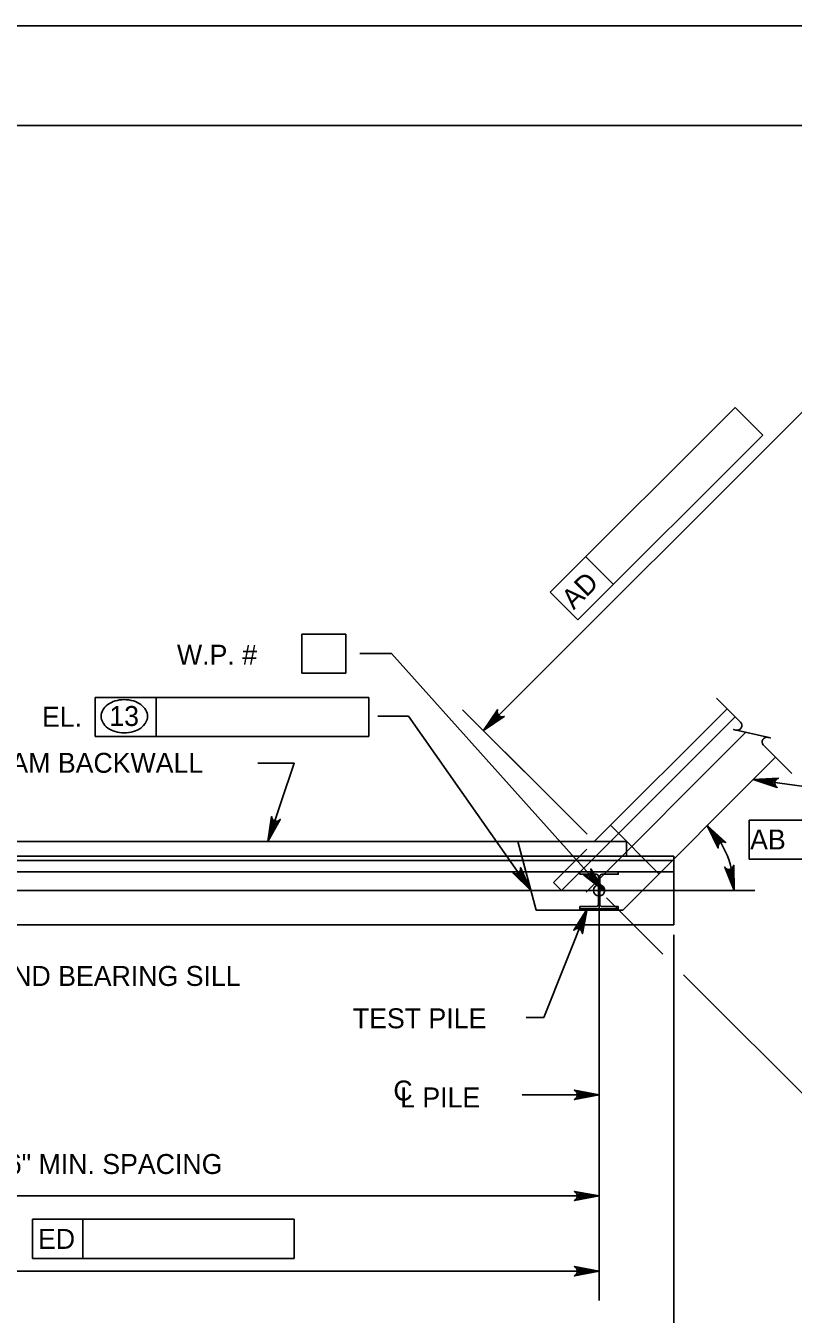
# Model space of a CAD drawing. Extents: x 638304 to 640306, y 296653 to 298435.
# Drawn here: x 639645.7 to 639761.1, y 298241.7 to 298435.5 of the extents above; entities that cross this region are included whole.
import ezdxf

# ---------------------------------------------------------------- set-up
doc = ezdxf.new("R2010")
doc.units = 0
for name, color, linetype in [('2', 7, 'Continuous'), ('3', 7, 'Continuous'), ('Level 2', 7, 'Continuous'), ('Level 3', 7, 'Continuous'), ('Level 4', 7, 'Continuous'), ('Level 5', 7, 'Continuous'), ('Level 8', 7, 'Continuous'), ('PLT-BNDY', 7, 'Continuous')]:
    doc.layers.add(name, color=color, linetype=linetype)

# ---------------------------------------------------------------- blocks, each defined once
blk = doc.blocks.new('HPILE')
at = {"layer": '3'}
for p, q in [((-0.12, -2.66), (-0.12, 2.66)), ((0.12, 2.66), (0.12, -2.66)), ((-3.67, -3.1), (-0.56, -3.1))]:
    blk.add_line(p, q, dxfattribs=at)
for points in [[(-0.56, 3.1), (-3.67, 3.1), (-3.67, 3.54), (3.67, 3.54), (3.67, 3.1), (0.56, 3.1)], [(0.56, -3.1), (3.67, -3.1), (3.67, -3.54), (-3.67, -3.54), (-3.67, -3.1)]]:
    blk.add_lwpolyline(points, dxfattribs=at)
for centre, start, end in [((-0.56, 2.66), 0, 90), ((0.56, 2.66), 90, 180), ((-0.56, -2.66), 270, 0), ((0.56, -2.66), 180, 270)]:
    blk.add_arc(centre, 0.438, start, end, dxfattribs=at)

msp = doc.modelspace()

# ---------------------------------------------------------------- linework, layer by layer
at = {"layer": '2'}
msp.add_line((639316.46, 298420.46), (640102.46, 298420.46), dxfattribs=at)
at = {"layer": 'Level 2'}
for p, q in [((639731.17, 298312.79), (639751.13, 298332.75)), ((639735.45, 298302.48), (639758.43, 298325.46)), ((639733.61, 298315.23), (639740.9, 298307.93)), ((639731.17, 298312.79), (639485.08, 298312.79)), ((639722.44, 298302.48), (639719.69, 298312.79)), ((639743.13, 298300.27), (639743.13, 298310.17)), ((639726.24, 298305.43), (639725.02, 298306.64)), ((639735.45, 298302.48), (639722.44, 298302.48)), ((639743.13, 298300.27), (639474.26, 298300.27))]:
    msp.add_line(p, q, dxfattribs=at)
at = {"layer": 'Level 3'}
for p, q in [((639726.24, 298305.43), (639752.35, 298331.54)), ((639736.04, 298312.79), (639731.17, 298312.79)), ((639736.04, 298310.58), (639736.04, 298312.79)), ((639743.13, 298310.58), (639474.26, 298310.58)), ((639730.03, 298311.65), (639725.02, 298306.64)), ((639743.13, 298310.17), (639743.13, 298310.58)), ((639474.26, 298309.93), (639743.13, 298309.93)), ((639474.26, 298308.21), (639743.13, 298308.21))]:
    msp.add_line(p, q, dxfattribs=at)
at = {"layer": 'Level 4'}
for p, q in [((639714.5, 298329.47), (639773.87, 298388.83)), ((639724.54, 298350.28), (639752.33, 298378.06)), ((639752.33, 298378.06), (639756.49, 298373.89)), ((639728.71, 298346.11), (639756.49, 298373.89)), ((639729.88, 298355.61), (639734.05, 298351.44)), ((639724.54, 298350.28), (639728.71, 298346.11)), ((639687.22, 298338.08), (639687.22, 298343.97)), ((639687.22, 298343.97), (639693.8, 298343.97)), ((639693.8, 298338.08), (639693.8, 298343.97)), ((639693.8, 298338.08), (639687.22, 298338.08)), ((639656.15, 298334.46), (639697.28, 298334.46)), ((639656.15, 298328.56), (639656.15, 298334.46)), ((639665.31, 298328.56), (639665.31, 298334.46)), ((639697.28, 298334.46), (639697.28, 298328.56)), ((639730.09, 298313.88), (639711.38, 298332.59)), ((639697.28, 298328.56), (639656.15, 298328.56)), ((639729.93, 298305.19), (639753.96, 298329.21)), ((639730.09, 298313.88), (639717.72, 298326.25)), ((639754.44, 298316), (639789.67, 298316)), ((639754.44, 298310.11), (639754.44, 298316)), ((639789.67, 298310.11), (639754.44, 298310.11)), ((639755.33, 298305.43), (639460.73, 298305.43)), ((639732.99, 298304.34), (639741.49, 298295.84)), ((639731.9, 298303.89), (639731.9, 298243.75)), ((639743.13, 298298.73), (639743.13, 298229.63)), ((639744.56, 298292.76), (639770.58, 298266.75)), ((639723.61, 298286.3), (639720.92, 298286.3)), ((639731.9, 298274.68), (639720.31, 298274.68)), ((639484.34, 298259.48), (639731.9, 298259.48)), ((639646.74, 298255.98), (639686.04, 298255.98)), ((639646.74, 298255.98), (639646.74, 298250.08)), ((639654.29, 298255.98), (639654.29, 298250.08)), ((639686.04, 298255.98), (639686.04, 298250.08)), ((639646.74, 298250.08), (639686.04, 298250.08)), ((639612.15, 298248.17), (639731.9, 298248.17))]:
    msp.add_line(p, q, dxfattribs=at)
for points in [[(639732.6, 298305.43), (639700.69, 298341.04), (639695.93, 298341.04)], [(639721.65, 298305.43), (639703.24, 298331.62), (639698.64, 298331.62)], [(639714.5, 298329.47), (639716.64, 298332.59), (639716.58, 298332.25), (639716.65, 298331.96), (639716.8, 298331.76), (639717, 298331.61), (639717.28, 298331.54), (639717.63, 298331.6), (639714.5, 298329.47), (639717.28, 298331.54), (639717, 298331.61), (639714.5, 298329.47), (639716.8, 298331.76), (639716.65, 298331.96), (639714.5, 298329.47), (639716.58, 298332.25)], [(639682.1, 298312.79), (639686.08, 298324.56), (639680.59, 298324.56)], [(639755.08, 298322.11), (639768.93, 298320.2), (639772.29, 298323.55)], [(639755.08, 298322.11), (639758.86, 298322.3), (639758.55, 298322.14), (639758.37, 298321.91), (639758.29, 298321.67), (639758.3, 298321.42), (639758.41, 298321.15), (639758.67, 298320.91), (639755.08, 298322.11), (639758.41, 298321.15), (639758.3, 298321.42), (639755.08, 298322.11), (639758.29, 298321.67), (639758.37, 298321.91), (639755.08, 298322.11), (639758.55, 298322.14)], [(639682.1, 298312.79), (639682.64, 298316.54), (639682.73, 298316.21), (639682.92, 298315.99), (639683.14, 298315.87), (639683.39, 298315.83), (639683.68, 298315.89), (639683.96, 298316.1), (639682.1, 298312.79), (639683.68, 298315.89), (639683.39, 298315.83), (639682.1, 298312.79), (639683.14, 298315.87), (639682.92, 298315.99), (639682.1, 298312.79), (639682.73, 298316.21)], [(639748.15, 298315.19), (639750.94, 298312.62), (639750.61, 298312.73), (639750.32, 298312.71), (639750.1, 298312.59), (639749.92, 298312.41), (639749.81, 298312.14), (639749.82, 298311.79), (639748.15, 298315.19), (639749.81, 298312.14), (639749.92, 298312.41), (639748.15, 298315.19), (639750.1, 298312.59), (639750.32, 298312.71), (639748.15, 298315.19), (639750.61, 298312.73)], [(639721.65, 298305.43), (639718.94, 298308.07), (639719.27, 298307.95), (639719.56, 298307.97), (639719.79, 298308.08), (639719.97, 298308.26), (639720.09, 298308.52), (639720.09, 298308.87), (639721.65, 298305.43), (639720.09, 298308.52), (639719.97, 298308.26), (639721.65, 298305.43), (639719.79, 298308.08), (639719.56, 298307.97), (639721.65, 298305.43), (639719.27, 298307.95)], [(639732.6, 298305.43), (639729.6, 298307.73), (639729.94, 298307.65), (639730.23, 298307.71), (639730.44, 298307.84), (639730.6, 298308.04), (639730.69, 298308.32), (639730.64, 298308.66), (639732.6, 298305.43), (639730.69, 298308.32), (639730.6, 298308.04), (639732.6, 298305.43), (639730.44, 298307.84), (639730.23, 298307.71), (639732.6, 298305.43), (639729.94, 298307.65)], [(639752.2, 298305.43), (639750.78, 298308.94), (639751.03, 298308.7), (639751.31, 298308.6), (639751.56, 298308.61), (639751.8, 298308.7), (639752.01, 298308.89), (639752.15, 298309.21), (639752.2, 298305.43), (639752.01, 298308.89), (639751.8, 298308.7), (639752.2, 298305.43), (639751.56, 298308.61), (639751.31, 298308.6), (639752.2, 298305.43), (639751.03, 298308.7)], [(639730.11, 298302.65), (639723.61, 298286.3)], [(639730.11, 298302.65), (639729.38, 298298.93), (639729.3, 298299.27), (639729.13, 298299.5), (639728.91, 298299.63), (639728.66, 298299.69), (639728.38, 298299.64), (639728.09, 298299.45), (639730.11, 298302.65), (639728.38, 298299.64), (639728.66, 298299.69), (639730.11, 298302.65), (639728.91, 298299.63), (639729.13, 298299.5), (639730.11, 298302.65), (639729.3, 298299.27)], [(639731.9, 298274.68), (639728.18, 298273.99), (639728.47, 298274.19), (639728.61, 298274.43), (639728.66, 298274.68), (639728.61, 298274.93), (639728.47, 298275.18), (639728.18, 298275.38), (639731.9, 298274.68), (639728.47, 298275.18), (639728.61, 298274.93), (639731.9, 298274.68), (639728.66, 298274.68), (639728.61, 298274.43), (639731.9, 298274.68), (639728.47, 298274.19)], [(639731.9, 298259.48), (639728.18, 298258.78), (639728.47, 298258.98), (639728.61, 298259.23), (639728.66, 298259.48), (639728.61, 298259.73), (639728.47, 298259.98), (639728.18, 298260.18), (639731.9, 298259.48), (639728.47, 298259.98), (639728.61, 298259.73), (639731.9, 298259.48), (639728.66, 298259.48), (639728.61, 298259.23), (639731.9, 298259.48), (639728.47, 298258.98)], [(639731.9, 298248.17), (639728.18, 298247.47), (639728.47, 298247.67), (639728.61, 298247.92), (639728.66, 298248.17), (639728.61, 298248.42), (639728.47, 298248.67), (639728.18, 298248.87), (639731.9, 298248.17), (639728.47, 298248.67), (639728.61, 298248.42), (639731.9, 298248.17), (639728.66, 298248.17), (639728.61, 298247.92), (639731.9, 298248.17), (639728.47, 298247.67)]]:
    msp.add_lwpolyline(points, dxfattribs=at)
for points in [[(639716.24, 298331.9), (639716.93, 298331.2), (639714.5, 298329.47)], [(639755.08, 298322.11), (639757.96, 298321.47), (639758.03, 298321.95)], [(639682.1, 298312.79), (639683.28, 298315.51), (639682.82, 298315.66)], [(639721.65, 298305.43), (639720.16, 298307.98), (639719.76, 298307.7)], [(639732.6, 298305.43), (639730.82, 298307.79), (639730.45, 298307.46)], [(639730.11, 298302.65), (639728.79, 298300), (639729.25, 298299.82)], [(639728.96, 298274.19), (639728.96, 298275.17), (639731.9, 298274.68)], [(639728.96, 298259.97), (639728.96, 298258.99), (639731.9, 298259.48)], [(639728.96, 298248.66), (639728.96, 298247.68), (639731.9, 298248.17)]]:
    msp.add_lwpolyline(points, close=True, dxfattribs=at)
msp.add_circle((639731.9, 298305.43), 0.849, dxfattribs=at)
for centre, radius, start, end in [((639659.65, 298331.15), 2.75, 125.6316, 149.9767), ((639660.18, 298330.42), 3.65, 106.5358, 125.6316), ((639660.52, 298329.26), 4.86, 90, 106.5358), ((639660.52, 298329.26), 4.86, 73.4642, 90), ((639660.87, 298330.42), 3.65, 54.3684, 73.4642), ((639661.39, 298331.15), 2.75, 30.0233, 54.3684), ((639658.85, 298331.62), 1.82, 149.9767, 180), ((639658.85, 298331.62), 1.82, 180, 210.0233), ((639662.2, 298331.62), 1.82, 0, 30.0233), ((639662.2, 298331.62), 1.82, 329.9767, 0), ((639659.65, 298332.08), 2.75, 210.0233, 234.3684), ((639660.18, 298332.81), 3.65, 234.3684, 253.4642), ((639660.87, 298332.81), 3.65, 286.5358, 305.6316), ((639661.39, 298332.08), 2.75, 305.6316, 329.9767), ((639660.52, 298333.97), 4.86, 253.4642, 270), ((639660.52, 298333.97), 4.86, 270, 286.5358), ((639738.39, 298305.43), 13.8, 359.9984, 45.0026)]:
    msp.add_arc(centre, radius, start, end, dxfattribs=at)
at = {"layer": 'Level 8'}
for p, q in [((639749.57, 298334.32), (639753.15, 298330.74)), ((639756.58, 298327.31), (639760.89, 298323))]:
    msp.add_line(p, q, dxfattribs=at)
msp.add_lwpolyline([(639752.46, 298329.55), (639752.12, 298329.63), (639757.65, 298328.37), (639757.28, 298328.45)], dxfattribs=at)
for centre, start, end in [((639752.65, 298330.24), 255, 45), ((639757.12, 298327.76), 77.1328, 219.6714)]:
    msp.add_arc(centre, 0.709, start, end, dxfattribs=at)
at = {"layer": 'PLT-BNDY'}
msp.add_lwpolyline([(639276.46, 298435.46), (640117.46, 298435.46), (640117.46, 297841.46), (639276.46, 297841.46)], close=True, dxfattribs=at)

# ---------------------------------------------------------------- block references
at = {"layer": 'Level 3', "xscale": 0.7859001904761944, "yscale": 0.7859001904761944}
msp.add_blockref('HPILE', (639731.9, 298305.43), dxfattribs=at)

# ---------------------------------------------------------------- texts
at = {"layer": 'Level 4'}
msp.add_text('AD', height=3, rotation=45, dxfattribs=at).set_placement((639728.08, 298347.53))
for s, height, p in [('W.P. #', 3, (639668.44, 298339.37)), ('EL.', 3, (639648.15, 298330.04)), ('13', 3, (639658.27, 298330.16)), ('AB', 3, (639754.6, 298311.59)), ('L PILES AND BEARING SILL', 3.0001, (639625.16, 298291.07)), ('TEST PILE', 3, (639694.88, 298284.7)), ('C', 3, (639700.97, 298273.84)), ('L PILE', 3, (639701.99, 298272.8)), ('2\'-6" MIN. SPACING', 3.0001, (639638.53, 298262.79)), ('ED', 3, (639647.55, 298251.53))]:
    msp.add_text(s, height=height, dxfattribs=at).set_placement(p)
at = {"layer": 'Level 5'}
msp.add_text('3 1/8" GLULAM BACKWALL', height=3.0001, dxfattribs=at).set_placement((639621.46, 298323.12))

doc.saveas('drawing.dxf')
